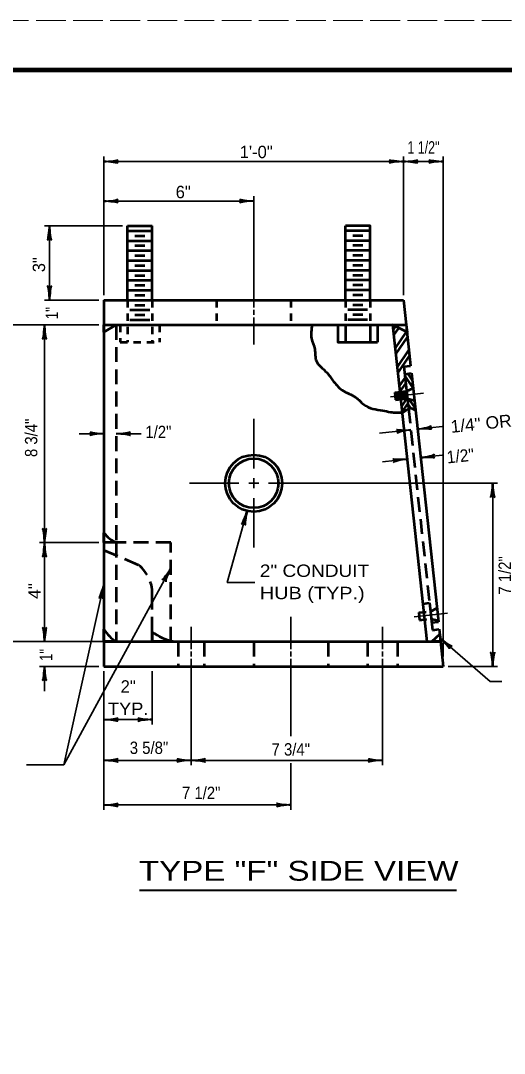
# Model space of a CAD drawing. Extents: x -1 to 679, y 0 to 440.
# Drawn here: x 190.5 to 288.2, y 231 to 439.6 of the extents above; entities that cross this region are included whole.
import ezdxf
from ezdxf.enums import TextEntityAlignment as Align

# ---------------------------------------------------------------- set-up
doc = ezdxf.new("R2010")
doc.units = 0
for name, pattern in [('LONG_DASHED', [7.5, 6, -1.5]), ('MEDIUM_DASHED', [4.5, 3, -1.5]), ('SHORT_DASHED', [2.7, 1.5, -1.2])]:
    doc.linetypes.add(name, pattern=pattern)
doc.layers.add('1', color=7, linetype='Continuous', lineweight=53)
doc.layers.add('61', color=7, linetype='Continuous', lineweight=35)

msp = doc.modelspace()

# ---------------------------------------------------------------- linework, layer by layer
at = {"layer": '1', "lineweight": 35}
for p, q in [((207.337, 384.171), (207.337, 412.171)), ((267.837, 384.171), (267.837, 412.171)), ((275.837, 311.171), (275.837, 412.171)), ((237.587, 403.171), (207.337, 403.171)), ((237.587, 404.171), (237.587, 381.671)), ((211.087, 398.171), (195.337, 398.171)), ((196.337, 398.171), (196.337, 383.171)), ((206.337, 383.171), (195.337, 383.171)), ((237.587, 381.171), (237.587, 380.171)), ((206.337, 378.171), (185.337, 378.171)), ((195.337, 334.171), (195.337, 378.171)), ((237.587, 379.671), (237.587, 374.171)), ((265.171, 363.641), (271.882, 364.366)), ((237.587, 349.171), (237.587, 359.171)), ((262.95, 356.268), (269.288, 356.953)), ((270.656, 357.101), (275.626, 357.638)), ((202.337, 356.171), (207.337, 356.171)), ((209.837, 356.171), (214.837, 356.171)), ((263.573, 350.505), (268.544, 351.043)), ((271.279, 351.338), (275.661, 351.812)), ((237.587, 347.171), (237.587, 345.171)), ((234.587, 346.171), (224.587, 346.171)), ((238.587, 346.171), (236.587, 346.171)), ((240.587, 346.171), (286.837, 346.171)), ((285.837, 346.171), (285.837, 309.171)), ((237.587, 343.171), (237.587, 333.171)), ((206.337, 334.171), (194.337, 334.171)), ((195.337, 334.171), (195.337, 314.171)), ((220.837, 329.013), (199.256, 289.269)), ((207.337, 325.714), (199.256, 289.269)), ((269.982, 319.171), (276.693, 319.896)), ((224.962, 317.171), (224.962, 312.671)), ((245.087, 319.171), (245.087, 312.671)), ((263.587, 317.171), (263.587, 312.671)), ((207.337, 314.171), (185.337, 314.171)), ((224.962, 312.171), (224.962, 311.171)), ((245.087, 312.171), (245.087, 311.171)), ((263.587, 312.171), (263.587, 311.171)), ((206.337, 309.171), (194.337, 309.171)), ((195.337, 309.171), (195.337, 304.171)), ((224.962, 310.671), (224.962, 289.171)), ((245.087, 310.671), (245.087, 295.073)), ((263.587, 310.671), (263.587, 289.171)), ((276.837, 309.171), (286.837, 309.171)), ((207.337, 308.171), (207.337, 280.171)), ((217.087, 308.171), (217.087, 297.416)), ((217.087, 298.416), (207.337, 298.416)), ((199.256, 289.269), (191.685, 289.269)), ((245.087, 289.604), (245.087, 280.171)), ((207.337, 281.171), (245.087, 281.171))]:
    msp.add_line(p, q, dxfattribs=at)
at = {"layer": '1'}
for p, q in [((212.087, 383.171), (212.087, 398.171)), ((212.087, 398.171), (217.087, 398.171)), ((212.087, 397.171), (217.087, 397.171)), ((217.087, 383.171), (217.087, 398.171)), ((256.087, 383.171), (256.087, 398.171)), ((261.087, 397.171), (256.087, 397.171)), ((212.087, 395.171), (217.087, 395.171)), ((213.587, 396.171), (215.587, 396.171)), ((261.087, 395.171), (256.087, 395.171)), ((259.587, 396.171), (257.587, 396.171)), ((212.087, 393.171), (217.087, 393.171)), ((213.587, 394.171), (215.587, 394.171)), ((261.087, 393.171), (256.087, 393.171)), ((259.587, 394.171), (257.587, 394.171)), ((212.087, 391.171), (217.087, 391.171)), ((213.587, 392.171), (215.587, 392.171)), ((261.087, 391.171), (256.087, 391.171)), ((259.587, 392.171), (257.587, 392.171)), ((212.087, 389.171), (217.087, 389.171)), ((213.587, 390.171), (215.587, 390.171)), ((213.587, 388.171), (215.587, 388.171)), ((261.087, 389.171), (256.087, 389.171)), ((259.587, 390.171), (257.587, 390.171)), ((259.587, 388.171), (257.587, 388.171)), ((212.087, 387.171), (217.087, 387.171)), ((213.587, 386.171), (215.587, 386.171)), ((261.087, 387.171), (256.087, 387.171)), ((259.587, 386.171), (257.587, 386.171)), ((212.087, 385.171), (217.087, 385.171)), ((213.587, 384.171), (215.587, 384.171)), ((261.087, 385.171), (256.087, 385.171)), ((259.587, 384.171), (257.587, 384.171)), ((207.337, 383.171), (267.837, 383.171)), ((213.587, 382.171), (215.587, 382.171)), ((259.587, 382.171), (257.587, 382.171)), ((212.587, 381.171), (216.587, 381.171)), ((213.587, 380.171), (215.587, 380.171)), ((260.587, 381.171), (256.587, 381.171)), ((259.587, 380.171), (257.587, 380.171)), ((207.337, 378.171), (207.337, 334.171)), ((212.587, 379.171), (216.587, 379.171)), ((256.087, 378.171), (256.087, 374.671)), ((260.587, 379.171), (256.587, 379.171)), ((261.087, 378.171), (261.087, 374.671)), ((262.587, 378.171), (262.587, 374.671)), ((265.719, 377.173), (266.2, 377.871)), ((268.378, 378.171), (268.539, 376.68)), ((265.843, 376.03), (266.874, 377.528)), ((266.131, 373.364), (268.447, 376.726)), ((266.255, 372.221), (268.646, 375.692)), ((266.543, 369.554), (268.934, 373.025)), ((266.667, 368.411), (269.058, 371.882)), ((267.908, 369.72), (269.275, 369.868)), ((267.908, 369.72), (268.822, 361.269)), ((266.955, 365.744), (268.15, 367.48)), ((268.069, 368.229), (269.437, 368.377)), ((269.745, 365.524), (268.104, 367.906)), ((269.575, 367.092), (268.742, 368.302)), ((269.436, 368.377), (274.867, 318.148)), ((267.079, 364.601), (268.274, 366.337)), ((268.446, 364.749), (269.759, 365.394)), ((266.084, 364.494), (268.446, 364.749)), ((266.084, 364.494), (266.245, 363.003)), ((266.245, 363.003), (268.607, 363.258)), ((266.359, 364.272), (266.467, 363.278)), ((266.581, 364.548), (266.742, 363.056)), ((266.857, 364.326), (266.964, 363.332)), ((267.354, 364.38), (267.461, 363.385)), ((267.4, 361.629), (268.515, 363.248)), ((267.575, 364.655), (267.737, 363.164)), ((267.851, 364.433), (267.958, 363.439)), ((268.072, 364.709), (268.234, 363.217)), ((268.285, 364.48), (268.392, 363.486)), ((268.607, 363.258), (270.028, 362.909)), ((270.19, 361.408), (268.979, 363.166)), ((267.586, 360.577), (268.719, 362.222)), ((269.327, 361.339), (268.719, 362.222)), ((209.837, 334.171), (207.337, 334.171)), ((271.703, 321.829), (273.069, 321.977)), ((273.069, 321.977), (273.661, 316.509)), ((273.5, 318), (274.867, 318.148)), ((207.337, 314.171), (207.337, 316.671)), ((217.087, 314.171), (217.087, 316.171)), ((217.087, 316.171), (217.087, 314.171)), ((273.661, 316.509), (275.028, 316.657)), ((275.028, 316.657), (275.296, 314.171)), ((207.337, 314.171), (221.316, 314.171)), ((209.837, 314.171), (207.337, 314.171)), ((221.316, 314.171), (217.087, 314.171)), ((221.316, 314.171), (272.531, 314.171)), ((272.531, 314.171), (275.297, 314.171)), ((275.297, 314.171), (275.837, 309.171)), ((207.337, 309.171), (275.837, 309.171))]:
    msp.add_line(p, q, dxfattribs=at)
at = {"layer": '1', "linetype": 'SHORT_DASHED'}
for p, q in [((212.087, 383.171), (212.087, 374.671)), ((217.087, 383.171), (217.087, 374.671)), ((230.087, 383.171), (230.087, 378.171)), ((245.087, 383.171), (245.087, 378.171)), ((256.087, 383.171), (256.087, 378.171)), ((261.087, 383.171), (261.087, 378.171)), ((218.587, 378.171), (218.587, 374.671)), ((270.896, 320.024), (271.057, 318.532)), ((271.057, 318.532), (273.418, 318.788)), ((273.418, 318.788), (274.839, 318.438))]:
    msp.add_line(p, q, dxfattribs=at)
at = {"layer": '1', "linetype": 'MEDIUM_DASHED'}
for p, q in [((268.822, 361.269), (273.07, 321.977)), ((220.837, 334.171), (209.837, 334.171)), ((220.837, 314.171), (220.837, 334.171)), ((207.337, 332.671), (214.386, 329.617)), ((217.087, 316.171), (217.087, 323.325)), ((222.337, 314.171), (222.337, 309.171)), ((227.587, 314.171), (227.587, 309.171)), ((237.587, 314.171), (237.587, 309.171)), ((252.587, 314.171), (252.587, 309.171)), ((260.587, 314.171), (260.587, 309.171)), ((266.587, 314.171), (266.587, 309.171))]:
    msp.add_line(p, q, dxfattribs=at)
at = {"layer": '1', "lineweight": 40}
msp.add_line((214.486, 263.929), (278.56, 263.929), dxfattribs=at)
at = {"layer": '1', "lineweight": 35}
for points in [[(207.337, 411.171), (267.837, 411.171), (275.837, 411.171)], [(236.268, 340.574), (232.235, 326.08), (237.796, 326.08)], [(275.222, 314.856), (285.333, 306.122), (287.655, 306.122)], [(207.337, 290.171), (224.962, 290.171), (263.587, 290.171)]]:
    msp.add_lwpolyline(points, dxfattribs=at)
at = {"layer": '1'}
for points in [[(261.087, 383.171), (261.087, 398.171), (256.087, 398.171)], [(207.337, 383.171), (207.337, 378.171), (268.378, 378.171)], [(267.837, 383.171), (268.378, 378.171), (269.275, 369.868)], [(254.587, 378.171), (254.587, 374.671), (262.587, 374.671)], [(268.539, 376.68), (265.612, 378.171), (268.378, 378.171)], [(265.612, 378.171), (267.079, 364.601), (272.531, 314.171)], [(270.069, 361.002), (270.125, 360.972), (270.243, 360.904)], [(209.837, 334.171), (207.337, 334.171), (207.337, 336.171)], [(207.337, 334.171), (207.337, 314.171), (207.337, 309.171)]]:
    msp.add_lwpolyline(points, dxfattribs=at)
for points in [[(207.337, 378.171), (209.837, 378.171), (207.337, 376.671)], [(273.531, 314.171), (275.135, 315.662), (275.296, 314.171)]]:
    msp.add_lwpolyline(points, close=True, dxfattribs=at)
at = {"layer": '1', "linetype": 'MEDIUM_DASHED'}
msp.add_lwpolyline([(209.837, 378.171), (209.837, 334.171), (209.837, 314.171)], dxfattribs=at)
at = {"layer": '1', "linetype": 'SHORT_DASHED'}
for points in [[(210.587, 378.171), (210.587, 374.671), (218.587, 374.671)], [(270.896, 320.024), (273.257, 320.279), (274.571, 320.924)]]:
    msp.add_lwpolyline(points, dxfattribs=at)
at = {"layer": '1'}
for radius in [5.75, 5]:
    msp.add_circle((237.587, 346.171), radius, dxfattribs=at)
for centre, radius, start, end in [((212, 339.437), 5.693, 215.00934, 247.67105), ((213.528, 320.362), 7.207, 210.80234, 239.19766), ((223.777, 324.844), 10.953, 232.35749, 257.01513)]:
    msp.add_arc(centre, radius, start, end, dxfattribs=at)
at = {"layer": '1', "linetype": 'MEDIUM_DASHED'}
msp.add_arc((209.635, 323.851), 7.471, 355.96163, 50.51063, dxfattribs=at)
at = {"layer": '1', "lineweight": 40}
for centre, major_axis, ratio, start_param, end_param in [((208.428, 411.447), (-1.786, -0.156), 0.122415, 0.8963533, 3.1415927), ((208.428, 411.447), (-1.786, -0.156), 0.122415, 0.8963533, 3.1415927), ((208.458, 410.959), (-1.756, 0.176), 0.07063, 3.1407148, 5.41811), ((208.458, 410.959), (-1.756, 0.176), 0.07063, 3.1407148, 5.41811), ((266.746, 410.895), (1.786, 0.156), 0.122415, 0.8963533, 3.1415927), ((266.746, 410.895), (1.786, 0.156), 0.122415, 0.8963533, 3.1415927), ((266.717, 411.383), (1.756, -0.176), 0.07063, 3.1407148, 5.41811), ((266.717, 411.383), (1.756, -0.176), 0.07063, 3.1407148, 5.41811), ((268.928, 411.447), (-1.786, -0.156), 0.122415, 0.8963533, 3.1415927), ((268.928, 411.447), (-1.786, -0.156), 0.122415, 0.8963533, 3.1415927), ((268.958, 410.959), (-1.756, 0.176), 0.07063, 3.1407148, 5.41811), ((268.958, 410.959), (-1.756, 0.176), 0.07063, 3.1407148, 5.41811), ((274.746, 410.895), (1.786, 0.156), 0.122415, 0.8963533, 3.1415927), ((274.717, 411.383), (1.756, -0.176), 0.07063, 3.1407148, 5.41811), ((208.428, 403.447), (-1.786, -0.156), 0.122415, 0.8963533, 3.1415927), ((208.428, 403.447), (-1.786, -0.156), 0.122415, 0.8963533, 3.1415927), ((208.458, 402.959), (-1.756, 0.176), 0.07063, 3.1407148, 5.41811), ((208.458, 402.959), (-1.756, 0.176), 0.07063, 3.1407148, 5.41811), ((236.496, 402.895), (1.786, 0.156), 0.122415, 0.8963533, 3.1415927), ((236.496, 402.895), (1.786, 0.156), 0.122415, 0.8963533, 3.1415927), ((236.467, 403.383), (1.756, -0.176), 0.07063, 3.1407148, 5.41811), ((236.467, 403.383), (1.756, -0.176), 0.07063, 3.1407148, 5.41811), ((196.126, 397.051), (0.176, 1.756), 0.07063, 3.1407148, 5.41811), ((196.613, 397.08), (-0.156, 1.786), 0.122415, 0.8963533, 3.1415927), ((196.061, 384.262), (0.156, -1.786), 0.122415, 0.8963533, 3.1415927), ((196.549, 384.292), (-0.176, -1.756), 0.07063, 3.1407148, 5.41811), ((195.126, 377.051), (0.176, 1.756), 0.07063, 3.1407148, 5.41811), ((195.613, 377.08), (-0.156, 1.786), 0.122415, 0.8963533, 3.1415927), ((268.152, 357.043), (1.765, 0.014), 0.07063, 3.1407148, 5.41811), ((268.152, 357.043), (1.765, 0.014), 0.07063, 3.1407148, 5.41811), ((268.233, 356.561), (1.759, 0.347), 0.122415, 0.8963533, 3.1415927), ((268.233, 356.561), (1.759, 0.347), 0.122415, 0.8963533, 3.1415927), ((271.711, 357.493), (-1.759, -0.347), 0.122415, 0.8963533, 3.1415927), ((271.711, 357.493), (-1.759, -0.347), 0.122415, 0.8963533, 3.1415927), ((271.792, 357.011), (-1.765, -0.014), 0.07063, 3.1407148, 5.41811), ((271.792, 357.011), (-1.765, -0.014), 0.07063, 3.1407148, 5.41811), ((206.246, 355.895), (1.786, 0.156), 0.122415, 0.8963533, 3.1415927), ((206.217, 356.383), (1.756, -0.176), 0.07063, 3.1407148, 5.41811), ((210.928, 356.447), (-1.786, -0.156), 0.122415, 0.8963533, 3.1415927), ((210.958, 355.959), (-1.756, 0.176), 0.07063, 3.1407148, 5.41811), ((267.408, 351.133), (1.765, 0.014), 0.07063, 3.1407148, 5.41811), ((267.408, 351.133), (1.765, 0.014), 0.07063, 3.1407148, 5.41811), ((267.489, 350.651), (1.759, 0.347), 0.122415, 0.8963533, 3.1415927), ((267.489, 350.651), (1.759, 0.347), 0.122415, 0.8963533, 3.1415927), ((272.334, 351.73), (-1.759, -0.347), 0.122415, 0.8963533, 3.1415927), ((272.334, 351.73), (-1.759, -0.347), 0.122415, 0.8963533, 3.1415927), ((272.415, 351.248), (-1.765, -0.014), 0.07063, 3.1407148, 5.41811), ((272.415, 351.248), (-1.765, -0.014), 0.07063, 3.1407148, 5.41811), ((285.625, 345.051), (0.176, 1.756), 0.07063, 3.1407148, 5.41811), ((286.113, 345.08), (-0.156, 1.786), 0.122415, 0.8963533, 3.1415927), ((235.764, 339.552), (-0.64, -1.645), 0.07063, 6.2823074, 8.5597026), ((236.242, 339.449), (0.328, 1.762), 0.122415, 0.8963533, 3.1415927), ((195.061, 335.262), (0.156, -1.786), 0.122415, 0.8963533, 3.1415927), ((195.549, 335.292), (-0.176, -1.756), 0.07063, 3.1407148, 5.41811), ((195.126, 333.051), (0.176, 1.756), 0.07063, 3.1407148, 5.41811), ((195.613, 333.08), (-0.156, 1.786), 0.122415, 0.8963533, 3.1415927), ((220.117, 328.129), (-0.993, -1.46), 0.07063, 6.2823074, 8.5597026), ((220.559, 327.922), (0.715, 1.644), 0.122415, 0.8963533, 3.1415927), ((206.888, 324.666), (-0.552, -1.677), 0.07063, 6.2823074, 8.5597026), ((206.888, 324.666), (-0.552, -1.677), 0.07063, 6.2823074, 8.5597026), ((207.371, 324.589), (0.234, 1.777), 0.122415, 0.8963533, 3.1415927), ((207.371, 324.589), (0.234, 1.777), 0.122415, 0.8963533, 3.1415927), ((195.061, 315.262), (0.156, -1.786), 0.122415, 0.8963533, 3.1415927), ((195.549, 315.292), (-0.176, -1.756), 0.07063, 3.1407148, 5.41811), ((275.932, 313.964), (-1.214, 1.281), 0.07063, 3.1407148, 5.41811), ((276.229, 314.352), (-1.453, 1.049), 0.122415, 0.8963533, 3.1415927), ((285.561, 310.262), (0.156, -1.786), 0.122415, 0.8963533, 3.1415927), ((286.049, 310.292), (-0.176, -1.756), 0.07063, 3.1407148, 5.41811), ((195.126, 308.051), (0.176, 1.756), 0.07063, 3.1407148, 5.41811), ((195.613, 308.08), (-0.156, 1.786), 0.122415, 0.8963533, 3.1415927), ((208.428, 298.693), (-1.786, -0.156), 0.122415, 0.8963533, 3.1415927), ((208.428, 298.693), (-1.786, -0.156), 0.122415, 0.8963533, 3.1415927), ((208.458, 298.205), (-1.756, 0.176), 0.07063, 3.1407148, 5.41811), ((208.458, 298.205), (-1.756, 0.176), 0.07063, 3.1407148, 5.41811), ((215.996, 298.14), (1.786, 0.156), 0.122415, 0.8963533, 3.1415927), ((215.967, 298.628), (1.756, -0.176), 0.07063, 3.1407148, 5.41811), ((208.428, 290.447), (-1.786, -0.156), 0.122415, 0.8963533, 3.1415927), ((208.428, 290.447), (-1.786, -0.156), 0.122415, 0.8963533, 3.1415927), ((208.458, 289.959), (-1.756, 0.176), 0.07063, 3.1407148, 5.41811), ((208.458, 289.959), (-1.756, 0.176), 0.07063, 3.1407148, 5.41811), ((223.871, 289.895), (1.786, 0.156), 0.122415, 0.8963533, 3.1415927), ((223.871, 289.895), (1.786, 0.156), 0.122415, 0.8963533, 3.1415927), ((223.842, 290.383), (1.756, -0.176), 0.07063, 3.1407148, 5.41811), ((223.842, 290.383), (1.756, -0.176), 0.07063, 3.1407148, 5.41811), ((226.053, 290.447), (-1.786, -0.156), 0.122415, 0.8963533, 3.1415927), ((226.053, 290.447), (-1.786, -0.156), 0.122415, 0.8963533, 3.1415927), ((226.083, 289.959), (-1.756, 0.176), 0.07063, 3.1407148, 5.41811), ((226.083, 289.959), (-1.756, 0.176), 0.07063, 3.1407148, 5.41811), ((262.496, 289.895), (1.786, 0.156), 0.122415, 0.8963533, 3.1415927), ((262.467, 290.383), (1.756, -0.176), 0.07063, 3.1407148, 5.41811), ((208.428, 281.447), (-1.786, -0.156), 0.122415, 0.8963533, 3.1415927), ((208.458, 280.959), (-1.756, 0.176), 0.07063, 3.1407148, 5.41811), ((243.996, 280.895), (1.786, 0.156), 0.122415, 0.8963533, 3.1415927), ((243.967, 281.383), (1.756, -0.176), 0.07063, 3.1407148, 5.41811)]:
    msp.add_ellipse(centre, major_axis=major_axis, ratio=ratio, start_param=start_param, end_param=end_param, dxfattribs=at)
at = {"layer": '1'}
msp.add_spline([(249.378, 378.171), (249.266, 375.403), (249.899, 373.258), (250.24, 370.82), (251.069, 369.748), (252.336, 368.529), (253.506, 367.017), (255.455, 364.97), (258.185, 363.507), (259.793, 362.093), (261.645, 361.216), (263.594, 360.875), (265.203, 360.533), (266.47, 360.436), (268.127, 360.728), (268.822, 361.269), (269.589, 361.265), (270.125, 360.972)], degree=3, dxfattribs=at)
at = {"layer": '61', "linetype": 'LONG_DASHED', "lineweight": 13}
msp.add_line((-1.376, 439.629), (678.644, 439.629), dxfattribs=at)
at = {"layer": '61', "lineweight": 158}
msp.add_lwpolyline([(667.664, 429.629), (28.624, 429.629), (28.624, 9.609)], dxfattribs=at)

# ---------------------------------------------------------------- texts
at = {"layer": '1'}
for s, height, width, p in [('1 1/2"', 2.5, 0.75, (271.862, 412.774)), ('1/2"', 2.5, 0.9, (218.333, 355.278)), ('TYP.', 2.5, 1.1, (212.234, 299.359)), ('3 5/8"', 2.5, 0.9, (216.438, 291.466)), ('7 3/4"', 2.5, 0.9, (245.068, 291.147)), ('7 1/2"', 2.5, 0.9, (226.979, 282.361)), ('TYPE "F" SIDE VIEW', 4, 1.25, (246.674, 265.862))]:
    msp.add_text(s, height=height, dxfattribs=dict(at, width=width)).set_placement(p, align=Align.CENTER)
for s, p in [('1\'-0"', (238.085, 411.847)), ('6"', (223.345, 403.758)), ('2"', (212.234, 303.859))]:
    msp.add_text(s, height=2.5, dxfattribs=at).set_placement(p, align=Align.CENTER)
msp.add_text('3"', height=2.5, rotation=90, dxfattribs=at).set_placement((195.451, 390.323), align=Align.CENTER)
for s, rotation, width, p in [('1"', 90, 0.8, (198.061, 380.532)), ('1/4" OR 11 GA.', 6, 1.05, (289.539, 357.603)), ('8 3/4"', 90, 0.9, (193.885, 355.336)), ('1/2"', 6, 0.95, (279.45, 350.443)), ('7 1/2"', 90, 0.9, (289.533, 327.537)), ('4"', 90, 1.05, (194.537, 324.396)), ('1"', 90, 0.8, (196.887, 311.471))]:
    msp.add_text(s, height=2.5, rotation=rotation, dxfattribs=dict(at, width=width)).set_placement(p, align=Align.CENTER)
for s, width, p in [('2" CONDUIT', 1.15, (238.82, 327.239)), ('HUB (TYP.)', 1.2, (238.82, 322.739))]:
    msp.add_text(s, height=2.5, dxfattribs=dict(at, width=width)).set_placement(p)

doc.saveas('drawing.dxf')
